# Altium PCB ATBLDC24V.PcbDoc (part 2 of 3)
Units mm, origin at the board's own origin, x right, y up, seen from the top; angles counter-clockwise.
Board outline 135 x 125 mm, 4 copper layers (Top Layer, GND, PWR/Signal, Bottom Layer), stack 1.716 mm thick; 340 components, 168 nets, 921 pads, 872 vias.
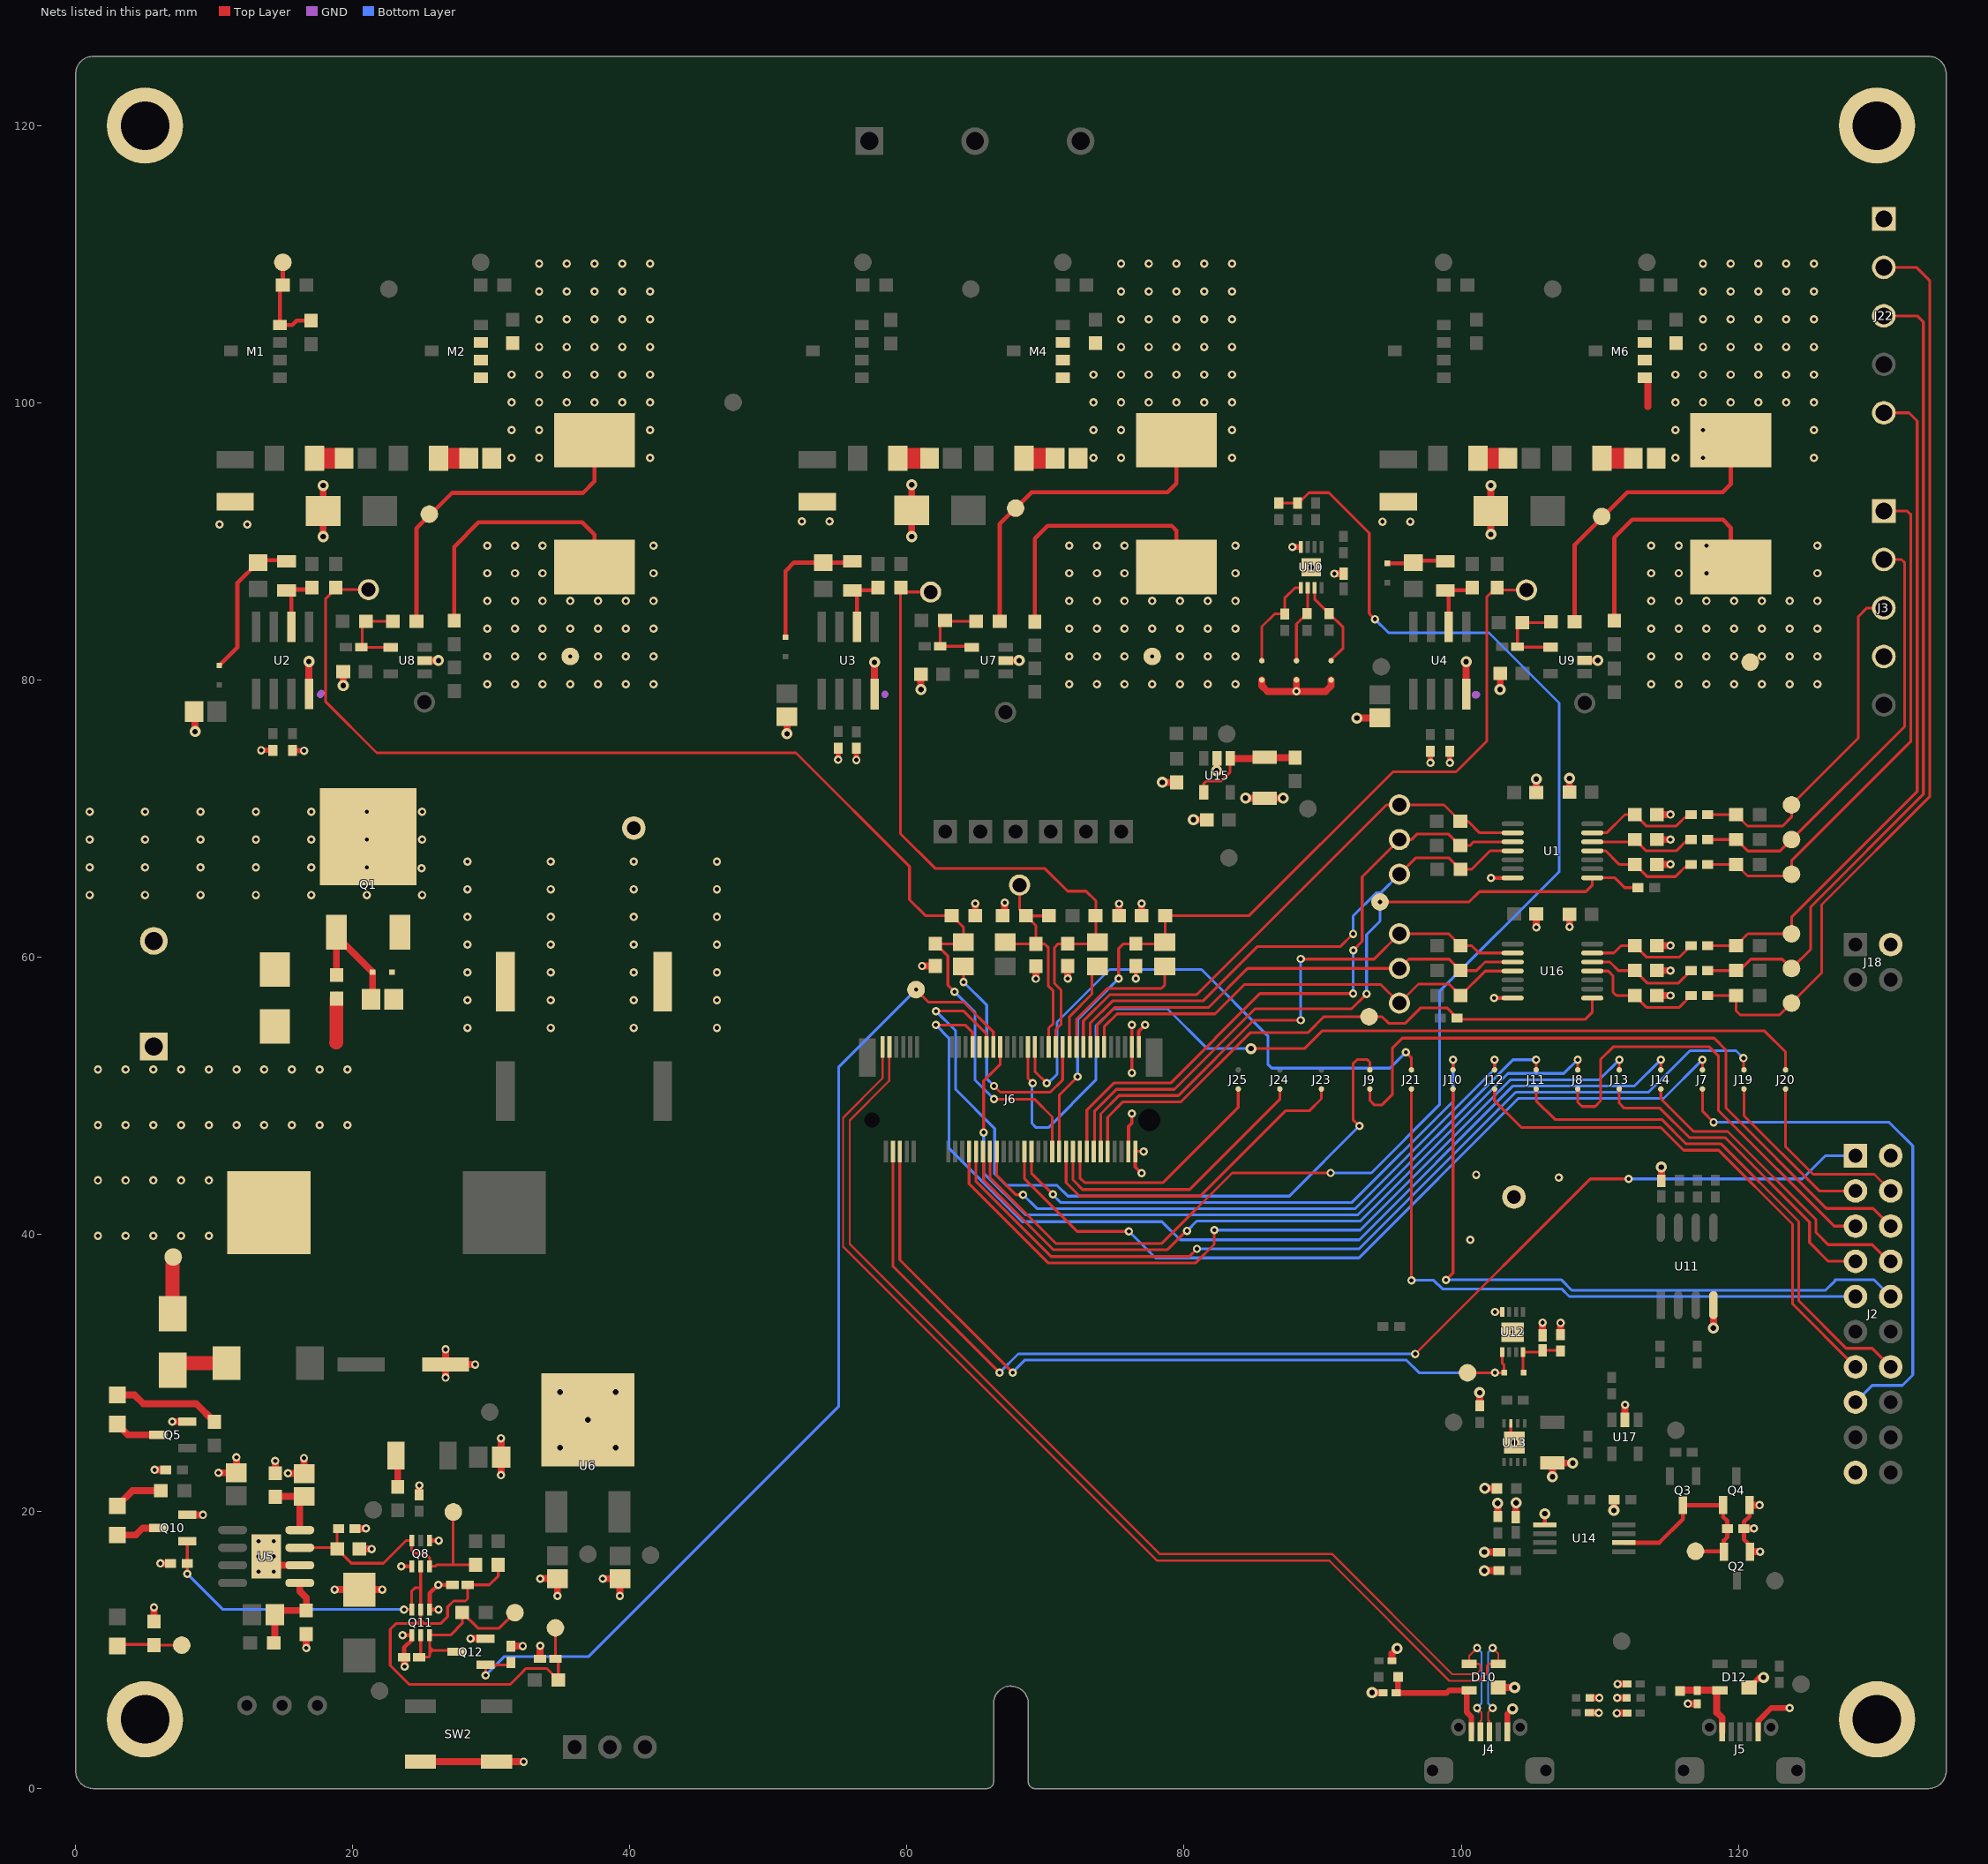
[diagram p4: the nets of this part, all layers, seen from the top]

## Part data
C1 C2 C39 C44 C45: library part A01-0087, "Ceramic capacitor, SMD 0603, X7R, 16V, +/-10 %"
C3 C8 C13: library part A01-0586, "Ceramic capacitor, SMD 1210, X7S , 50V, ±10%"
C4 C9 C14 C19 C23 C24: library part A01-0392, "Ceramic capacitor, SMD 0805, X7R, 50V, ±10 %"
C5 C10 C15: library part A01-0498, "CAP CER 4.7UF 50V 10% X5R 0805"
C6 C7 C11 C12 C16 C17: library part A01-0194, "Ceramic capacitor, SMD 0805, X7R, 50V, ±10 %"
C18 C20: library part A01-0721, "Cap Aluminum Lytic 220uF 50V 20% (10 X 10.2mm) SMD 150mA 2000h 105°C T/R"
C21 C30 C31 C55: library part A01-0321, "Ceramic capacitor, SMD 0402, C0G, 50V, +/-5%"
C22: library part A01-0394, "10uF/25V,SMD tantalum capacitor, precision molded chip, 6032-28 case,"
C25: library part A01-0283, "SMD aluminium electrolytic capasitor Ø8mm, Max rippel=0.25(@105degC, 100kHz), Tan=0.08"
C26 C57: library part A01-0214, "Ceramic capacitor, SMD 0805, X7R, 50V, ±10 %"
C27 C28: library part A01-0634, "Ceramic capacitor, SMD 0805, X5R, 25V, ±10%"
C29 C32: library part A01-0046, "Ceramic capacitor, SMD 0402, X7R, 25V, +/-10%"
C33 C34 C37: library part A01-0027, "Ceramic capacitor, SMD 0402, NP0, 50V, +/-10% (de16673)"
C35 C36 C38: library part A01-0367, "Ceramic capacitor, SMD 0603, X7R, 50V, ±10 %"
C40: library part A01-0381, "Capacitor, Ceramic, 1uF, 100V, 1206, X7R"
C41 C42 C43 C46 C47 C48: library part A01-0083, "Ceramic capacitor, SMD 0603, NP0, 50V,  ±5 %"
C49 C50 C56 C59: library part A01-0101, "Ceramic capacitor, SMD 0603, X7R, 50V, ±10 %"
C51: library part A01-0113, "Ceramic capacitor, SMD 0603, X7R, 50V, ±10 %"
C52 C54: library part A01-0050, "Ceramic capacitor, SMD 0402, X7R, 25V, +/-10%"
C53: library part A01-0038, "Ceramic capacitor, SMD 0402, X7R, 50V, +/-10%"
C60 C61 C65 C66: library part A01-0246, "Ceramic capacitor, SMD 0402, X7R, 16V, +/-10%"
C62: library part A01-0347, "Ceramic capacitor, SMD 0402, X5R, 6.3V, +/-20% (de33687)"
C63: library part A01-0324, "SMD tantalum capacitor, ESR = 1.7, 3216-18 (EIA) 1206,"
C64: library part A01-0377, "Ceramic capacitor, SMD 0603, X5R, 10V, 10% (de31036)"
CONN1: library part A08-2466, "PHOENIX CONTACT  GMKDS 3/ 2-7,62  TERMINAL BLOCK, WIRE TO BRD, 2POS, 12AWG"
CONN2: library part A08-2465, "TERMINAL BLOCK, WIRE TO BRD, 3POS, 12AWG"
D1 D3 D5 D18: library part A04-0049, "Schottky diode, If:200mA, Vf:0.35V, Vrrm:30V, SOD-523"
D2 D4 D6 D8: library part A04-0021, "Bidirectional Transient suppression diode, 600W, V(rm)=58.1V, I(rm)=1uA (at Vrm), V(br)=68V, V(cl)=121V (at Ipp = 33A), SMD (SMB package)"
D7: library part A04-0180, "Zener DIODE 28V, 500MW, SOD80"
D9: library part A04-0138, "1A, 100V, Schottky Barrier Rectifier, SMA"
D10 D12: library part A06-0236, "Double rail-to-rail USB ESD protection diode"
D11: library part A10-0019, "LED, Yellow, Wave length=591nm, SMD 0805, ±70°"
D13: library part A04-0133, "Zener diode SOD-523, 5.6V, 200mW"
D14 D15: library part A10-0017, "LED, Red, Wave length=639nm, SMD 0805, ±70°"
E1 E2 E3 E4 E5 E6: library part A08-0053, "2.8mm adhesive feet,diam 8.0mm"
F1: library part A02-0509, "SMD holder and fuse 5x20mm, Fast, 6.3A, 250V"
F2: library part A02-0504, "PolySwitch Resettable fuse 0.75A, 30V"
J1: library part A08-0191, "1x6 pin header, 2.54mm pitch, THM Pin-In-Paste"
J2: library part A08-1513, "Pin header, 2x10, Right Angle, 2.54mm, THM, Pin In Paste"
J3 J22: library part A08-2349, "SCREW-TERMINAL 5-POLE, 3.5MM, Through Hole"
J4 J5: library part A08-2112, "Micro USB AB Connector, Standard SMT + DIP"
J6: library part A08-2293, "M.2 (NGFF) Sockets for Adapter PCB"
J7 J8 J9 J10 J11 J12 J13 J14 J19 J20 J21 J23 J24 J25: library part A09-0473, "Default closed SMD strap"
J15 J16 J17: library part A08-1416
J18: library part A08-1519, "Pin header, 2x2, Right Angle, 2.54mm, THT, Pin In Paste"
J26: library part A08-1799, "1x3 pin header, 2.54mm pitch, Pin-in-Paste THM, 1mm hole"
JS1: library part A08-0543, "Jumper cap for 2.54mm pinheader"
L1 L6: library part A03-0035, "SMD RF inductor 0603. Z=470Ohm (@100MHz), Max R(dc)=0.65Ohm, Max current=1A"
L2 L3 L4 L5: library part A03-0004, "SMD RF inductor 0805. Z=1000Ohm (@100MHz), Max R(dc)=0.45Ohm, Max current=200mA"
LABEL1: library part A09-0611, "PCBA identification label PP Top White Gloss"
M1 M2 M3 M4 M5 M6: library part A05-0152, "60V, 4.7mA , 89A, Single N−Channel MOSFET, SO−8FL"
Q1: library part A05-0166, "MOSFET N-CH 60V 40A 16MOHM DPAK"
Q2 Q3: library part A05-0087, "P-ch. MOSFET. -30V, -3.7A continuous,RDS(ON)=0.05Ohm@VGS=-4,5V, RDS(ON)=0.08Ohm@VGS=-2.5V"
Q4 Q5 Q10: library part A05-0085, "N-Channel MOSFET. 60V, 0.300A continuous, 1.2A Peak. RDS(ON) = 3.8Ohm@VGS=4.5V, VGS(th)<2.5V"
Q8 Q11: library part A05-0051, "Dual N-Channel MOSFET, 60V, 115mA cont,RDS(ON) < 7.5 Ohm @50mA@5V, SOT-363"
Q12: library part A05-0001, "General purpose SMD small signal BJT transistor. Polarity:NPN, Body:SOT23, P(tot)=0.25W, V(ceo)=45V, I(c)=0.1A, h(fe)=200/450, f(t)=100MHz"
R1 R3 R4 R13 R14 R23 R24 R81 R82 R83 R84 R85 R86 R88 R89 R90 R91 R92 R93 R97 R101 R102 R112 R121: library part A02-0260, "Thick film resistor, SMD 0402, 1/16W, 1%"
R2 R9 R12 R19 R22 R29: library part A02-0994, "RESISTOR, 1206, 0R82, 1%, 0.5W"
R5 R15 R25: library part A02-0294, "Thick film resistor, SMD 0805, 0.125W, 1%"
R6 R16 R39 R41 R46 R49: library part A02-0960, "1.0K 0.1%, resistor in 0603 at 100mW, TEMPCO 10ppm/C, Max V=75V"
R7 R11 R17 R21 R27 R31 R33 R120: library part A02-0122, "Thick film resistor, SMD 0603, 1/10W, 1%"
R8 R10 R18 R20 R28 R47 R57 R58 R59: library part A02-0001, "Thick film resistor, SMD 0603, 1/10W, 1%"
R26 R30 R48: library part A02-0996, "RES, METAL STRIP, R02, 1%, 5W, SMD 4527"
R32: library part A02-0113, "Thick film resistor, SMD 0603, 1/10W, 1%"
R34: library part A02-0072, "Thick film resistor, SMD 0603, 1/10W, 1%"
R35: library part A02-0091, "Thick film resistor, SMD 0603, 1/10W, 1%"
R36: library part A02-0236, "Thick film resistor, SMD 0402, 1/16W, 1%"
R37 R42 R95 R98 R99: library part A02-0284, "Thick film resistor, SMD 0402, 1/16W, 1%"
R38: library part A02-0090, "Thick film resistor, SMD 0603, 1/10W, 1%"
R40 R67 R70 R72 R109 R110 R111: library part A02-0076, "Thick film resistor, SMD 0603, 1/10W, 1%"
R43: library part A02-0200, "Thick film resistor, SMD 0402, 1/16W, 1%"
R44 R45 R50 R51 R52 R53 R54 R56: library part A02-0959, "10K 0.1%, resistor in 0603 at 100mW, TEMPCO 10ppm/C, Max V=75V"
R55: library part A02-0026, "Thick film resistor, SMD 0603, 1/10W, 1%"
R60 R61 R63 R106 R107 R108: library part A02-0114, "Thick film resistor, SMD 0603, 1/10W, 1%"
R62 R123: library part A02-0082, "Thick film resistor, SMD 0603, 1/10W, 1%"
R64 R68 R74: library part A02-1013, "Thick film resistor, SMD 0603, 1/10W, 1%"
R65 R69 R75 R80: library part A02-0997, "Thick film resistor, SMD 0603, 1/10W, 1%"
R66 R71 R104 R118: library part A02-0252, "Thick film resistor, SMD 0402, 1/16W, 1%"
R73 R76 R78 R113 R114 R115: library part A02-0163, "RES 0.0 OHM 1/16W 0402 SMD"
R79: library part A02-1014, "Thick film resistor, SMD 0603, 1/10W, 1%"
R87: library part A02-0178, "Thick film resistor, SMD 0402, 1/16W, 1%"
R94: library part A02-0242, "Thick film resistor, SMD 0402, 1/16W, 1%"
R96: library part A02-0247, "Thick film resistor, SMD 0402, 1/16W, 1%"
R100: library part A02-0202, "Thick film resistor, SMD 0402, 1/16W, 1%"
R105: library part A02-0163, "Thick film resistor, SMD 0402, 1/16W, 1%"
R117: library part A02-0042, "Thick film resistor, SMD 0603, 1/10W, 1%"
R119: library part A02-0129, "Thick film resistor, SMD 0603, 1/10W, 1%"
R122: library part A02-0040, "Thick film resistor, SMD 0603, 1/10W, 1%"
SW1: library part A08-0947, "Slide Switch, right angle 3 pol, 2 pos, (de20049)"
SW2: library part A08-0091, "6.2x6.2 mm SMD tact switch"
TP1 TP2 TP5 TP7 TP8 TP9 TP10 TP11 TP12 TP14 TP15 TP17 TP18 TP20 TP27 TP38 TP39 TP40 TP41 TP42 TP43 TP44 TP45 TP46 TP47 TP48 TP49 TP50 TP51 TP52 TP53 TP54 TP55 TP56 TP57 TP58 TP60 TP61 TP62 TP63 TP64 TP65 TP66 TP67 TP68 TP72: library part A08-0004, "Single SMD testpad"
TP3 TP4 TP6 TP13 TP16 TP19 TP21 TP23 TP25 TP26 TP28 TP35 TP36: library part A08-1748, "Single thru-hole testpin"
TP22 TP24: library part A08-1716, "THM Test Point, Without Base, 1.0mm Dia. Mounting"
U1 U16: library part A06-0852, "4-BIT BIDIRECTIONAL VOLTAGE-LEVEL TRANSLATOR 14TSSOP"
U2 U3 U4: library part A06-1250, "High Voltage, High and Low Side MOSFET Driver"
U5: library part A06-1249, "5 V to 20 V Adjustable LDO with Adjustable Current Limit and 3.3 V Logic Compatible Enable Input"
U6: library part A06-0137, "3-Terminal Positive Voltage Regulator"
U7 U8 U9: library part A06-1252, "Op Amps High Temp RR Op Amp 2.5V to 5.5V"
U10: library part A06-0633, "SINGLE DIGITAL TEMPERATURE SENSOR W/ SERIAL EEPROM, UDFN8"
U11: library part A06-1051, "8Mbit SPI serial flash memory"
U12: library part A06-1276, "ATSHA204 with 1-wire interface and UDFN8 package"
U13: library part A06-0957, "500mA LDO, ADJ, low noise, 8-DFN package"
U14: library part A06-0068, "Autoswitching 2:1 Power Mux"
U15: library part A06-1285, "OP AMP, CMOS 1MHZ RRI/O, SOT-23-5"
U17: library part A06-1087, "Single channel power switch, 1A, reverse block, active low enabled."

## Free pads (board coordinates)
  round 5.5 hole 3.5: 1(5,5) 1(5,120) 1(130,5) 1(130,120)

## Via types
v1: diameter 0.6, hole 0.3, Top Layer to Bottom Layer, 769 vias
v2: diameter 0.8, hole 0.4, Top Layer to Bottom Layer, 92 vias
v3: diameter 1, hole 0.5, Top Layer to Bottom Layer, 11 vias

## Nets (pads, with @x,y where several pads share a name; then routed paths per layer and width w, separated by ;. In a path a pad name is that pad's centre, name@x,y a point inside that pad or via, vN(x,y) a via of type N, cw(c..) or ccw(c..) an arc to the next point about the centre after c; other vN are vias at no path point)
A0: J15.2 R81.2 U10.7 | length 6.5
  Top Layer w0.2: U10.7@89.417,86.647 89.417,85.831 R81.2@90.457,84.791 90.477,84.791 91.475,83.793 91.475,82.304 90.608,81.438 J15.2@90.608,81.382
A1: J16.2 R85.2 U10.6 | length 5.6
  Top Layer w0.2: J16.2@88.108,81.382 88.108,84.033 88.917,84.842 U10.6@88.917,86.647
A2: J17.2 R82.2 U10.5 | length 7.1
  Top Layer w0.2: J17.2@85.608,81.382 85.608,83.843 86.537,84.772 R82.2@87.257,84.772 ; R82.2@87.257,84.766 R82.2@87.257,84.772 ; U10.5@88.417,86.647 88.015,86.647 87.257,85.89 R82.2@87.257,84.772
BEMF_UADC: C49.1 J6.42 L2.1 R64.2 R65.2 TP21.1 | length 88.3
  Top Layer w0.2: TP21.1@21.135,86.512 18.697,86.512 18.031,85.846 18.031,78.437 21.73,74.738 51.983,74.738 60.179,66.542 60.179,64.138 61.316,63 R65.2@63.22,63 64.079,62.142 L2.1@64.079,61.075 63.959,61.075 63.844,60.96 C49.1@62.056,60.96 62.951,60.065 62.951,57.983 v1(63.43,57.502) ; v1(66.277,49.75) 69.196,49.75 70.48,48.466 J6.42@70.48,45.975
  Bottom Layer w0.2: v1(63.43,57.502) 64.907,56.026 64.907,51.12 v1(66.277,49.75)
BEMF_UN: J6.46 J23.2 | length 24.7
  Top Layer w0.2: J6.46@71.48,45.975 71.48,43.728 72.455,42.753 81.164,42.753 87.317,48.905 89.038,48.905 89.907,49.773 J23.2@89.907,50.482
BEMF_UP: J6.45 L2.2 | length 17.4
  Top Layer w0.2: v1(64.079,58.203) L2.2@64.079,59.325 ; v1(66.277,50.7) 66.727,50.25 70.346,50.25 71.23,51.133 J6.45@71.23,53.525
  Bottom Layer w0.2: v1(64.079,58.203) 65.751,56.532 65.751,51.226 v1(66.277,50.7)
BEMF_VADC: C50.1 J6.43 L3.1 R68.2 R69.2 TP23.1 | length 49.9
  Top Layer w0.2: R68.2@59.539,86.657 59.528,86.668 59.528,68.906 62.048,66.386 69.963,66.386 71.592,64.756 72.924,64.756 73.633,64.047 L3.1@73.633,61.175 ; R68.2@59.55,86.668 59.875,86.342 TP23.1@61.708,86.342 ; J6.43@70.73,53.525 70.73,54.739 71.122,55.131 71.122,57.617 70.65,58.089 70.65,60.7 70.91,60.96 C50.1@71.586,60.96 73.418,60.96 L3.1@73.633,61.175 ; L3.1@73.733,61.075 L3.1@73.633,61.175
BEMF_VN: J6.48 J24.2 | length 20.7
  Top Layer w0.2: J6.48@71.98,45.975 71.98,43.921 72.667,43.235 80.407,43.235 86.907,49.735 J24.2@86.907,50.482
BEMF_VP: J6.47 L3.2 | length 6.4
  Top Layer w0.2: J6.47@71.73,53.525 71.73,55.723 73.348,57.341 L3.2@73.348,59.299
BEMF_WADC: C56.1 J6.44 L4.1 R74.2 R75.2 TP25.1 | length 64
  Top Layer w0.2: J6.44@70.98,45.975 70.98,50.032 v1(72.316,51.367) ; v1(75.277,58.45) 75.277,60.606 75.632,60.96 C56.1@76.514,60.96 78.485,60.96 L4.1@78.6,61.075 78.633,61.108 R75.2@78.633,63 84.708,63 95.076,73.369 99.622,73.369 101.851,75.597 101.851,86.011 102.594,86.753 102.854,86.492 TP25.1@104.708,86.492
  Bottom Layer w0.2: v1(72.316,51.367) 72.316,55.488 v1(75.277,58.45)
BEMF_WN: J6.50 J25.2 | length 17.1
  Top Layer w0.2: J6.50@72.48,45.975 72.48,44.057 72.804,43.733 78.484,43.733 83.907,49.157 J25.2@83.907,50.482
BEMF_WP: J6.49 L4.2 | length 10.7
  Top Layer w0.2: J6.49@72.23,53.525 72.23,55.52 74.448,57.738 78.358,57.738 78.6,57.98 L4.2@78.6,59.325
EDBG_ID1: D18.2 J6.6 TP62.1 U12.5 | length 59.1
  Top Layer w0.2: J6.6@59.48,45.975 59.48,38.156 v1(67.627,30.01) ; TP62.1@100.453,30.003 100.46,30.01 v1(102.427,30.01) D18.2@103.099,30.01 103.099,30.552 102.961,30.691 U12.5@102.961,31.493
  Bottom Layer w0.2: v1(67.627,30.01) 67.627,30.056 68.487,30.916 96.049,30.916 96.956,30.01 v1(102.427,30.01)
EDBG_ID2: J2.1@128.46,45.669 J6.4 | length 87.4
  Top Layer w0.2: J6.4@58.98,45.975 58.98,37.706 v1(66.677,30.01) ; v1(96.684,31.366) 109.319,44.002 109.321,44 v1(112.077,44)
  Bottom Layer w0.2: v1(66.677,30.01) 68.034,31.366 v1(96.684,31.366) ; v1(112.077,44) 124.612,44 126.281,45.669 J2.1@128.46,45.669
EDBG_USB_HS_N: D10.3 J4.2 J6.3 | length 82.8
  Top Layer w0.15: J6.3@58.73,53.525 58.72,53.515 58.72,51.071 55.864,48.214 55.864,39.299 78.222,16.94 90.661,16.94 99.348,8.254 101.084,8.254 101.385,8.555 101.385,8.877 101.264,8.998 D10.3@100.92,8.998 ; D10.3@100.575,8.998 100.575,9.577 v1(101.146,10.148) ; v1(101.146,5.822) 101.465,5.503 101.465,4.941 101.38,4.856 J4.2@101.38,4.1
  GND w0.15: 101.24,5.493 v1@101.24,5.624
  Bottom Layer w0.15: v1(101.146,5.822) 101.465,6.142 101.465,9.828 v1(101.146,10.148)
EDBG_USB_HS_P: D10.2 J4.3 J6.1 | length 84.5
  Top Layer w0.15: J6.1@58.23,53.525 58.24,53.515 58.24,51.27 55.384,48.413 55.384,39.1 78.024,16.46 90.462,16.46 99.149,7.774 101.283,7.774 101.865,8.356 101.865,8.877 101.986,8.998 D10.2@102.675,8.998 102.675,9.738 v1(102.265,10.148) ; J4.3@102.03,4.1 102.03,4.856 101.945,4.941 101.945,5.503 v1(102.265,5.822)
  Bottom Layer w0.15: v1(102.265,5.822) 101.945,6.142 101.945,9.828 v1(102.265,10.148)
ENCODER_A: J6.55 R107.1 TP35.1 U16.3 | length 34.1
  Top Layer w0.2: J6.55@73.73,53.525 73.73,55.111 74.976,56.357 81.756,56.357 84.579,59.181 TP35.1@95.538,59.181 96.21,59.852 99.13,59.852 R107.1@99.955,59.027 101.099,59.027 101.717,59.646 U16.3@103.711,59.646
ENCODER_B: J6.56 R106.1 TP26.1 U16.2 | length 41
  Top Layer w0.2: J6.56@73.98,45.975 73.98,48.69 75.302,50.011 79.593,50.011 85.023,55.441 v1(88.415,55.441) ; v1(88.415,59.866) 88.433,59.848 93.706,59.848 TP26.1@95.538,61.681 99.102,61.681 R106.1@99.955,60.827 100.748,60.827 101.28,60.296 U16.2@103.711,60.296
  Bottom Layer w0.2: v1(88.415,55.441) v1(88.415,59.866)
ENCODER_EN: J6.58 R112.1 TP72.1 U16.8 | length 43.6
  Top Layer w0.2: J6.58@74.48,45.975 74.477,45.979 74.477,48.435 75.604,49.561 79.78,49.561 84.763,54.544 88.927,54.544 90.081,55.698 TP72.1@93.346,55.698 94.291,55.698 94.294,55.696 ; TP72.1@93.346,55.696 94.294,55.696 ; R112.1@99.7,55.5 108.921,55.5 109.461,56.04 U16.8@109.461,57.046 ; R112.1@99.7,55.6 99.7,55.62 98.996,56.325 97.058,56.325 95.963,55.23 94.76,55.23 94.294,55.696
ENCODER_Z: J6.57 R108.1 TP36.1 U16.4 | length 34.4
  Top Layer w0.2: J6.57@74.23,53.525 74.23,54.975 75.163,55.907 82.231,55.907 84.346,58.022 94.197,58.022 TP36.1@95.538,56.681 96.91,58.052 99.13,58.052 R108.1@99.955,57.227 101.723,58.996 U16.4@103.711,58.996
EXT1_RXD: J6.26 J12.2 | length 44.2
  Top Layer w0.2: J6.26@66.48,45.975 66.48,44.23 67.861,42.85 v1(68.377,42.85) ; J12.2@102.407,51.863 v1(102.407,52.596)
  Bottom Layer w0.2: v1(68.377,42.85) 69.374,41.852 92.355,41.852 102.407,51.905 v1(102.407,52.596)
EXT1_TXD: J6.27 J11.2 | length 56.1
  Top Layer w0.2: v1(65.527,47.35) 65.527,51.062 66.73,52.265 J6.27@66.73,53.525 ; J11.2@105.407,51.863 v1@105.407,52.568
  Bottom Layer w0.2: v1(65.527,47.35) 65.527,44.412 68.537,41.403 92.541,41.403 103.735,52.596 v1(105.407,52.596)
GND: C1.2 C2.2 C3.2 C4.2 C8.2 C9.2 C13.2 C14.2 C18.2 C20.2 C21.2 C22.2 C23.2 C24.2 C25.2 C26.2 C27.2 C28.2 C29.1 C30.2 C31.2 C32.1 C35.2 C36.2 C38.2 C39.1 C40.2 C41.2 C42.2 C43.2 C44.2 C45.2 C46.2 C47.2 C48.2 C49.2 C50.2 C51.2 C52.2 C53.2 C54.2 C55.2 C56.2 C57.2 C59.2 C60.1 C61.2 C62.2 C63.2 C64.2 C65.2 C66.2 D2.2 D4.2 D6.2 D10.1 D12.1 D13.2 J2.2@131,45.669 J2.19@128.46,22.809 J3.4 J4.5 J5.5 J6.64 J6.65 J6.66 J6.67 J15.1 J16.1 J17.1 J18.2@131,60.909 J22.1 pad.1 Q1.3 Q2.1 Q4.2 Q5.2 Q8.1 Q8.4 Q10.2 Q11.1 Q11.4 Q12.2 R3.1 R4.2 R13.1 R14.2 R23.1 R24.2 R26.1 R30.1 R34.1 R35.2 R36.1 R37.1 R39.1 R40.1 R41.1 R42.1 R48.1 R49.1 R56.1 R65.1 R66.1 R69.1 R71.1 R75.1 R80.1 R93.1 R94.2 R98.1 R99.1 R100.1 R101.1 R118.1 R121.1 SW2.3 SW2.4 TP22.1 TP24.1 TP52.1 TP53.1 TP57.1 U1.7 U2.4 U3.4 U4.4 U5.2 U5.9 U6.2 U7.2 U8.2 U9.2 U10.4 U10.9 U11.4 U12.4 U12.9 U13.7 U13.9 U14.5 U15.2 U16.7 U17.2 | length 221.2
  Top Layer w0.2: J6.66@76.48,45.975 v1(77.079,45.975) ; v1(102.427,34.397) 102.431,34.393 U12.4@102.961,34.393
  Top Layer w0.25: J6.64@75.98,45.975 75.98,47.774 76.227,48.02 v1(76.227,48.7) ; v1(76.22,51.65) 76.23,51.661 J6.65@76.23,53.525 v1(76.23,55.101) ; J6.66@76.48,45.975 76.48,44.855 v1(76.935,44.4) ; J6.67@76.73,53.525 76.73,54.646 v1(77.185,55.101) ; U13.7@103.584,26.367 103.584,25.217 v2(103.834,24.967)
  Top Layer w0.3: v1(23.496,16.046) Q8.1@24.239,16.046 ; v1(23.602,11.075) Q11.1@24.25,11.075 24.25,10.725 23.698,10.174 C53.2@23.698,9.486 ; Q8.4@25.539,17.896 v1(26.196,17.896) ; v1(26.187,12.925) Q11.4@25.55,12.925 25.55,14.084 v1(26.166,14.7) C52.2@27.19,14.7 ; R41.1@27.317,84.273 27.317,89.608 29.084,91.375 36.558,91.375 37.45,90.483 R30.1@37.45,88.147 ; R39.1@69.221,84.192 69.221,90.197 70.148,91.123 79.111,91.123 79.45,90.784 R26.1@79.45,88.147 ; v1(76.514,58.448) C56.2@76.514,59.36 ; v1(102.147,65.718) U1.7@103.711,65.718 ; v1(102.375,57.046) U16.7@103.711,57.046 ; U14.5@106.034,19.042 v2(106.034,19.838) ; R49.1@111.043,84.269 111.043,90.271 112.334,91.562 118.889,91.562 119.45,91 R48.1@119.45,88.147 ; Q4.2@120.8,20.45 120.8,19.635 120.406,19.241 R101.1@120.406,18.767 120.406,17.98 120.85,17.536 Q2.1@120.85,17.1
  Top Layer w0.4: v1(13.389,74.925) R3.1@14.226,74.925 ; R4.2@15.646,74.895 v1(16.483,74.895) ; v1(55.035,74.244) R13.1@55.035,75.081 ; v1(56.343,74.226) R14.2@56.343,75.063 ; v1(87.807,89.597) 88.265,89.597 ; v1(97.775,74.019) R23.1@97.775,74.856 ; v1(99.175,74.019) R24.2@99.175,74.856 ; J4.5@103.33,4.1 103.33,5.386 v2(103.71,5.765) ; D12.1@120.775,7.297 121.5,8.022 v2(121.817,8.022) ; J5.5@121.43,4.1 121.43,4.872 122.365,5.807 v1(123.711,5.807)
  Top Layer w0.5: R40.1@5.65,12.05 v1(5.65,13.072) ; v1(5.702,23) R66.1@6.5,23 ; v1(6.104,16.25) R71.1@6.85,16.25 ; v1(6.968,26.479) Q5.2@8.05,26.479 ; Q10.2@8.05,19.75 v1(9.184,19.75) ; C4.2@8.542,77.709 8.614,77.637 v2(8.614,76.274) ; v1(10.305,22.787) C23.2@11.595,22.787 11.595,23.895 v1(11.6,23.9) ; U5.9@13.75,16.75 14.385,16.115 U5.2@16.175,16.115 ; R34.1@14.4,22.75 v1(14.4,23.644) ; v1(15.327,22.75) 16.476,22.75 C24.2@16.5,22.725 16.477,22.748 v1(16.477,23.85) ; v1(16.64,10.15) 16.64,10.797 R35.2@16.652,10.808 ; U2.4@16.833,78.987 v2(16.833,81.332) ; v2(17.857,90.343) D2.2@17.857,92.188 v2(17.857,94.033) ; v1(18.688,14.36) C22.2@20.47,14.36 v1(22.129,14.36) ; v2(19.31,79.598) C36.2@19.31,80.608 ; R36.1@20.164,18.768 v1(20.946,18.768) ; C51.2@20.471,17.289 v1(21.36,17.289) ; C53.2@23.698,9.486 23.74,9.444 v1(23.74,8.801) ; R118.1@24.797,21.205 v1(24.797,21.881) ; SW2.3@24.885,1.941 SW2.4@30.385,1.941 v1(32.335,1.941) ; U8.2@25.175,81.4 v2(26.182,81.4) ; v1(26.7,29.654) C25.2@26.7,30.6 ; v1(26.7,31.692) C25.2@26.7,30.6 ; v1(28.493,10.825) Q12.2@29.591,10.825 ; v1(28.833,30.6) C25.2@26.7,30.6 ; v1(30.702,22.618) C26.2@30.702,23.918 v1(30.702,25.283) ; R121.1@31.414,10.285 v1(32.272,10.285) ; C54.2@33.523,9.367 v1(33.523,10.297) ; v1(33.525,15.151) C27.2@34.767,15.151 v1(34.767,13.904) ; v1(38.037,15.145) C28.2@39.278,15.145 v1(39.278,13.898) ; v2(51.338,76.112) C9.2@51.338,77.358 ; U3.4@57.655,78.975 v2(57.655,81.27) ; v2(60.335,90.343) D4.2@60.335,92.231 v2(60.335,94.076) ; v2(61,79.312) C35.2@61,80.4 ; v1(61.087,59.36) C49.2@62.056,59.36 ; R65.1@64.92,63 v1(64.92,63.872) ; R80.1@67.052,63.232 v1(67.052,63.922) ; U7.2@67.125,81.4 v2(68.093,81.4) ; v1(69.3,58.437) C59.2@69.3,59.35 ; v1(71.599,58.458) C50.2@71.599,59.336 ; R69.1@75.297,62.977 v1(75.297,63.848) ; R75.1@76.933,63 v1(76.933,63.871) ; v2(78.426,72.609) R56.1@79.473,72.609 ; v2(80.671,69.912) C39.1@81.635,69.912 ; v2@82.371,73.471 U15.2@82.371,74.333 ; v2(84.432,71.467) C40.2@85.798,71.467 v2(87.149,71.467) ; J17.1@85.608,80.002 85.608,79.576 86.008,79.176 v1(88.108,79.176) ; J16.1@88.108,80.002 v1(88.108,79.176) ; J15.1@90.608,80.002 90.608,79.57 90.215,79.176 v1(88.108,79.176) ; v1(90.845,87.666) C60.1@91.507,87.666 ; v2(92.469,77.25) C14.2@93.845,77.25 ; v2(93.567,6.923) C30.2@94.357,6.923 ; C31.2@95.007,9.223 95.007,9.738 v2(95.376,10.107) ; U4.4@100.355,78.975 v2(100.355,81.323) ; R94.2@101.334,27.617 v2(101.334,28.571) ; v2(101.663,15.726) R98.1@102.722,15.726 ; v2(101.675,17.067) C65.2@102.734,17.067 ; v2(101.707,21.667) C64.2@102.585,21.667 ; v2(102.137,90.507) D6.2@102.137,92.188 v2(102.137,94.033) ; R99.1@102.634,19.642 v2(102.634,20.596) ; D10.1@102.675,7.298 v2(103.852,7.298) ; v2(102.8,79.3) 102.821,79.321 C38.2@102.821,80.466 C38.2@103.008,80.279 ; C66.2@103.934,19.592 103.934,20.6 v2(103.957,20.623) ; v1(105.416,62.14) C45.2@105.416,63.108 ; C2.2@105.416,71.868 v2(105.416,72.846) ; C62.2@105.867,32.714 v1(105.867,33.624) ; v2(106.584,22.499) C63.2@106.584,23.492 v2(108.049,23.492) ; R93.1@107.167,32.764 v1(107.167,33.605) ; v1(107.816,62.189) C44.2@107.816,63.081 ; C1.2@107.816,71.918 v2(107.816,72.896) ; U9.2@108.886,81.409 v2(109.852,81.409) ; C29.1@109.249,5.473 v1(109.928,5.473) ; R37.1@109.289,6.547 v1(109.968,6.547) ; v2(111.017,20.072) 111.034,20.089 R100.1@111.034,20.842 ; v1(111.235,5.447) C32.1@111.964,5.447 ; v1(111.261,6.547) R42.1@111.939,6.547 ; v1(111.285,7.547) C55.2@111.964,7.547 ; U17.2@111.822,26.601 v1(111.822,27.687) ; C48.2@114.13,57.228 v1(115.098,57.228) ; C46.2@114.13,59.028 v1(115.098,59.028) ; C47.2@114.13,60.828 v1(115.098,60.828) ; C43.2@114.13,66.691 v1(115.098,66.691) ; C41.2@114.131,68.484 v1(115.099,68.484) ; C42.2@114.131,70.284 v1(115.099,70.284) ; C61.2@114.445,43.84 v2(114.445,44.845) ; v1(116.36,6.122) C21.2@117.039,6.122 ; v2(118.205,33.236) U11.4@118.205,34.89 ; R101.1@120.406,18.767 v1(121.134,18.767) ; Q4.2@120.8,20.45 v1(121.528,20.45) ; Q2.1@120.85,17.1 v1(121.578,17.1)
  GND w0.5: v1(11.6,23.9) v1@11.6,23.958 ; 17.65,78.95 17.737,79.037 ; 58.4,78.95 58.415,78.966 ; 101.007,78.92 101.089,78.92 101.107,78.938 101.012,78.938 101,78.95 101.054,78.95 ; v2@103.9,20.68 v2(103.957,20.623)
  Bottom Layer w0.5: v1@23.711,8.771 v1(23.74,8.801)
  other v1: 13.2,15.65 14.3,15.65 13.2,16.75 14.3,16.75 13.2,17.85 14.3,17.85 103.711,32.943 100.647,39.604 107.039,44.087 101.084,44.294 28.281,54.897 34.281,54.897 40.281,54.897 46.281,54.897 28.281,56.897 34.281,56.897 40.281,56.897 46.281,56.897 28.281,58.897 34.281,58.897 40.281,58.897 46.281,58.897 28.281,60.897 34.281,60.897 40.281,60.897 46.281,60.897 28.281,62.897 34.281,62.897 40.281,62.897 46.281,62.897 28.281,64.897 34.281,64.897 40.281,64.897 46.281,64.897 28.281,66.897 34.281,66.897 40.281,66.897 46.281,66.897 29.7,79.697 31.7,79.697 33.7,79.697 35.7,79.697 37.7,79.697 39.7,79.697 41.7,79.697 71.7,79.697 73.7,79.697 75.7,79.697 77.7,79.697 79.7,79.697 81.7,79.697 83.7,79.697 113.7,79.697 115.7,79.697 117.7,79.697 119.7,79.697 121.7,79.697 123.7,79.697 125.7,79.697 29.7,81.697 31.7,81.697 33.7,81.697 35.7,81.697 37.7,81.697 39.7,81.697 41.7,81.697 71.7,81.697 73.7,81.697 75.7,81.697 77.7,81.697 79.7,81.697 81.7,81.697 83.7,81.697 113.7,81.697 115.7,81.697 117.7,81.697 119.7,81.697 121.7,81.697 123.7,81.697 125.7,81.697 29.7,83.697 31.7,83.697 33.7,83.697 35.7,83.697 37.7,83.697 39.7,83.697 41.7,83.697 71.7,83.697 73.7,83.697 75.7,83.697 77.7,83.697 79.7,83.697 81.7,83.697 83.7,83.697 113.7,83.697 115.7,83.697 117.7,83.697 119.7,83.697 121.7,83.697 123.7,83.697 125.7,83.697 29.7,85.697 31.7,85.697 33.7,85.697 35.7,85.697 37.7,85.697 39.7,85.697 41.7,85.697 71.7,85.697 73.7,85.697 75.7,85.697 77.7,85.697 79.7,85.697 81.7,85.697 83.7,85.697 113.7,85.697 115.7,85.697 117.7,85.697 119.7,85.697 121.7,85.697 123.7,85.697 125.7,85.697 29.7,87.697 31.7,87.697 33.7,87.697 41.7,87.697 71.7,87.697 73.7,87.697 75.7,87.697 83.7,87.697 113.7,87.697 115.7,87.697 117.7,87.697 125.7,87.697 29.7,89.697 31.7,89.697 33.7,89.697 41.7,89.697 71.7,89.697 73.7,89.697 75.7,89.697 83.7,89.697 113.7,89.697 115.7,89.697 117.7,89.697 125.7,89.697 10.379,91.226 12.379,91.226 52.405,91.432 54.405,91.432 94.322,91.421 96.322,91.421
  other v2: 34.969,24.612 38.969,24.612 36.969,26.612 34.969,28.612 38.969,28.612 82.35,73.45 89.167,88.122
GND_E: CONN1.2 D8.2 Q1.2
  other v1: 1.007,64.482 5.007,64.482 9.007,64.482 13.007,64.482 17.007,64.482 21.007,64.482 25.007,64.482 24.956,66.406 1.007,66.482 5.007,66.482 9.007,66.482 13.007,66.482 17.007,66.482 21.007,66.482 1.007,68.482 5.007,68.482 9.007,68.482 13.007,68.482 17.007,68.482 21.007,68.482 25.007,68.482 1.007,70.482 5.007,70.482 9.007,70.482 13.007,70.482 17.007,70.482 21.007,70.482 25.007,70.482
GPIO1: J6.18 J13.2 | length 59.1
  Top Layer w0.2: J6.18@64.48,45.975 64.48,43.64 70.182,37.938 80.837,37.938 82.168,39.269 82.168,40.289 v1(82.177,40.297) ; J13.2@111.407,51.863 v1@111.407,52.641
  Bottom Layer w0.2: v1(82.177,40.297) 92.708,40.297 103.565,51.154 109.965,51.154 v1(111.407,52.596)
GPIO2: J6.19 J14.2 | length 73.4
  Top Layer w0.2: v1(62.08,55.101) 64.203,55.101 64.73,54.574 J6.19@64.73,53.525 ; J14.2@114.407,51.863 v1(114.407,52.596)
  Bottom Layer w0.2: v1(62.08,55.101) 63.02,54.161 63.02,46.218 68.33,40.909 78.402,40.909 79.714,39.597 92.645,39.597 103.752,50.704 112.515,50.704 v1(114.407,52.596)
GPIO3: J6.20 J19.2 | length 66.9
  Top Layer w0.2: J6.20@64.98,45.975 64.98,43.801 70.394,38.388 80.368,38.388 v1(80.927,38.947) ; J19.2@120.372,51.976 v1@120.372,52.701
  Bottom Layer w0.2: v1(80.927,38.947) 92.631,38.947 103.938,50.254 113.527,50.254 116.519,53.246 119.835,53.246 v1(120.372,52.709)
GPIO4: J6.21
GPIO5: J6.22 J8.2 | length 53.5
  Top Layer w0.2: J6.22@65.48,45.975 65.53,45.925 65.53,43.908 70.548,38.89 78.799,38.89 80.179,40.269 80.201,40.247 v1(80.214,40.247) ; J8.2@108.407,51.863 v1@108.407,52.595
  Bottom Layer w0.2: v1(80.214,40.247) 80.92,40.953 92.728,40.953 103.379,51.604 107.414,51.604 v1(108.407,52.597)
GPIO6: J6.23 J9.2 | length 54.5
  Top Layer w0.2: v1(62.1,56.1) 64.094,56.1 65.73,54.464 J6.23@65.73,53.525 ; v1(92.647,47.809) 92.194,48.262 92.194,52.317 92.481,52.604 93.221,52.604 93.407,52.418 J9.2@93.407,51.863
  Bottom Layer w0.2: v1(62.1,56.1) 63.519,54.681 63.519,50.446 66.33,47.635 66.33,44.38 67.182,43.528 70.833,43.528 71.609,42.752 87.591,42.752 v1(92.647,47.809)
GPIO7: J6.24 R86.2 R87.2 | length 103.2
  Top Layer w0.2: J6.24@65.98,45.975 65.98,44.094 70.735,39.34 78.388,39.34 83.472,44.423 v1(90.573,44.423) ; R86.2@86.837,92.762 R87.2@88.187,92.762 88.267,92.762 89.017,93.512 90.451,93.512 93.365,90.598 93.365,84.797 v1(93.779,84.382)
  Bottom Layer w0.2: v1(90.573,44.423) 93.511,44.423 98.429,49.341 98.429,57.519 107.066,66.156 107.066,78.334 102.004,83.396 94.765,83.396 v1(93.779,84.382)
GPIO8: J6.25 Q12.1 R121.2 TP45.1 | length 76.5
  Top Layer w0.2: v1(29.591,8.173) Q12.1@29.591,8.925 31.254,8.925 R121.2@31.414,9.085 ; v1(60.65,57.65) 61.55,56.75 64.081,56.75 66.23,54.601 J6.25@66.23,53.525
  Bottom Layer w0.2: v1@29.568,8.151 v1(29.591,8.173) 30.95,9.532 37.038,9.532 55.062,27.556 55.062,52.062 v1(60.65,57.65)
GPIO9/ADC: J6.34 J7.2 | length 60
  Top Layer w0.2: J6.34@68.48,45.975 68.48,44.001 72.273,40.209 v1(76.018,40.209) ; J7.2@117.407,51.863 v1@117.407,52.588
  Top Layer w0.254: v1(76.018,40.209) v1@76.06,40.209
  Bottom Layer w0.2: v1(76.018,40.209) 77.93,38.297 80.657,38.297 ; 80.658,38.297 81.196,38.297 92.618,38.297 104.124,49.804 114.615,49.804 v1(117.407,52.596)
GPIO10: J6.35 J20.2 | length 69.7
  Top Layer w0.2: J6.35@68.73,53.525 68.73,51.246 v1(69.077,50.9) ; v2(84.827,53.4) 88.679,53.4 89.953,54.673 121.892,54.673 123.407,53.158 J20.2@123.407,51.863
  Bottom Layer w0.2: v1(69.077,50.9) 69.027,50.85 69.027,47.989 69.316,47.7 70.204,47.7 73.623,51.119 73.623,55.002 74.896,56.274 78.795,56.274 81.67,53.4 v2(84.827,53.4)
GPIO11: J6.36 J10.2 | length 39.6
  Top Layer w0.2: J6.36@68.98,45.975 68.98,44.42 v1(70.522,42.878) ; J10.2@99.407,51.863 v1(99.407,52.596)
  Bottom Layer w0.2: v1@70.512,42.868 71.078,42.302 92.124,42.302 99.407,49.585 v1(99.407,52.596)
GPIO12: J6.37 J21.2 | length 40.6
  Top Layer w0.2: J6.37@69.23,53.525 69.23,51.746 v1(70.077,50.9) ; v1(96.002,53.133) 96.407,52.728 J21.2@96.407,51.863
  Bottom Layer w0.2: v1(70.077,50.9) 70.188,50.9 70.835,51.546 70.835,55.314 74.624,59.103 81.252,59.103 86.044,54.312 86.044,52.269 86.328,51.984 94.853,51.984 v1(96.002,53.133)
HALL1: J6.51 R60.1 TP3.1 U1.2 | length 40.1
  Top Layer w0.2: J6.51@72.73,53.525 72.73,55.384 74.634,57.288 80.917,57.288 94.61,70.981 TP3.1@95.538,70.981 98.757,70.981 R60.1@99.932,69.806 100.491,69.806 101.329,68.968 U1.2@103.711,68.968
HALL2: J6.52 R61.1 TP4.1 U1.3 | length 47
  Top Layer w0.2: J6.52@72.98,45.975 72.98,48.963 74.929,50.911 79.02,50.911 85.475,57.366 v1(92.197,57.366) ; v1(92.206,60.498) 92.85,61.142 92.85,65.792 TP4.1@95.538,68.481 96.408,68.481 96.8,68.873 99.089,68.873 99.914,68.048 R61.1@99.939,68.048 100.618,68.048 100.888,68.318 U1.3@103.711,68.318
  Bottom Layer w0.2: v1(92.197,57.366) 92.206,57.375 v1(92.206,60.498)
HALL3: J6.53 R63.1 TP6.1 U1.4 | length 38.8
  Top Layer w0.2: J6.53@73.23,53.525 73.23,55.248 74.82,56.838 81.365,56.838 85.276,60.749 91.268,60.749 v1(92.2,61.68) ; TP6.1@95.538,65.981 96.712,67.154 99.13,67.154 R63.1@99.955,66.329 100.752,66.329 102.09,67.668 U1.4@103.711,67.668
  Bottom Layer w0.2: v1(92.2,61.68) 92.2,62.962 93.869,64.631 94.188,64.631 TP6.1@95.538,65.981
HALL_TRX_OE: J6.54 R1.1 TP60.1 U1.8 | length 53
  Top Layer w0.2: J6.54@73.48,45.975 73.53,46.025 73.53,48.877 75.115,50.461 79.299,50.461 85.112,56.274 92.093,56.274 v1(93.165,57.347) ; v1(94.138,63.981) 100.57,63.981 101.31,64.722 108.989,64.722 109.461,65.193 U1.8@109.461,65.718 111.089,65.718 111.793,65.014 R1.1@112.761,65.014
  Bottom Layer w0.2: v1(93.165,57.347) 93.165,61.622 94.138,62.596 v1(94.138,63.981)
INPUT_VOLTAGE_DETECTED: Q2.2 Q3.3 Q4.1 R101.2 TP65.1 U14.2 | length 14.2
  Top Layer w0.3: U14.2@111.734,17.742 114.297,17.742 116.004,19.449 Q3.3@116.004,20.142 ; Q3.3@116.012,20.449 118.899,20.449 Q4.1@118.9,20.45 118.9,19.613 119.206,19.307 R101.2@119.206,18.767 119.206,18.155 118.95,17.899 Q2.2@118.95,17.1 118.923,17.128 TP65.1@116.909,17.128
  Top Layer w0.5: Q3.3@116.004,20.142 Q3.3@116.034,20.112
MOTOR_VDC: C59.1 J6.41 L5.1 R79.2 R80.2 TP28.1 | length 16.7
  Top Layer w0.2: L5.1@67.1,61.075 67.225,60.95 C59.1@69.3,60.95 ; TP28.1@68.12,65.2 68.12,63.448 R80.2@68.59,62.977 69.3,62.268 C59.1@69.3,60.95 ; R80.2@68.956,62.977 R79.2@70.24,62.977 ; J6.41@70.23,53.525 70.23,54.876 70.555,55.2 70.555,57.548 70.2,57.903 70.2,60.684 69.933,60.95 C59.1@69.3,60.95
NetC5_1: C5.1 D1.1 R5.2 | length 10.8
  Top Layer w0.3: D1.1@10.357,81.038 11.667,82.347 11.667,86.994 R5.2@13.165,88.493 ; R5.2@12.631,88.637 C5.1@14.831,88.637
NetC5_2: C5.2 R8.1 U2.6 | length 4.7
  Top Layer w0.3: U2.6@15.563,83.837 15.563,86.179 15.216,86.526 16.871,86.526 R8.1@17.049,86.703
NetC6_1: C6.1 R2.1 | length 1.9
  Top Layer w1.5: R2.1@17.335,96 C6.1@19.235,96
NetC7_1: C7.1 R9.1 | length 1.8
  Top Layer w1.5: R9.1@26.335,96 C7.1@28.1,96
NetC7_2: C7.2 M2.1 R11.1 R16.1 R30.2 TP50.1 | length 23.9
  Top Layer w0.2: R30.2@37.45,96.043 R30.2@37.45,97.297
  Top Layer w0.3: R16.1@24.59,84.233 24.59,90.933 27.151,93.495 36.617,93.495 37.45,94.328 R30.2@37.45,96.043
  other v1: 31.45,96.028 33.45,96.028 41.45,96.028 31.45,98.028 33.45,98.028 41.45,98.028 31.45,100.028 33.45,100.028 35.45,100.028 37.45,100.028 39.45,100.028 41.45,100.028 31.45,102.028 33.45,102.028 35.45,102.028 37.45,102.028 39.45,102.028 41.45,102.028 33.45,104.028 35.45,104.028 37.45,104.028 39.45,104.028 41.45,104.028 33.45,106.028 35.45,106.028 37.45,106.028 39.45,106.028 41.45,106.028 33.45,108.028 35.45,108.028 37.45,108.028 39.45,108.028 41.45,108.028 33.45,110.028 35.45,110.028 37.45,110.028 39.45,110.028 41.45,110.028
NetC10_1: C10.1 D3.1 R15.2 | length 9.9
  Top Layer w0.3: D3.1@51.238,83.083 51.238,87.853 51.853,88.468 R15.2@53.95,88.468 55.95,88.468 C10.1@56.05,88.568
NetC10_2: C10.2 R18.1 U3.6 | length 4.8
  Top Layer w0.3: C10.2@56.05,86.468 C10.2@56.385,86.468 ; U3.6@56.385,83.825 C10.2@56.385,86.468 ; C10.2@56.385,86.646 C10.2@56.385,86.468 ; R18.1@57.9,86.668 57.7,86.468 C10.2@56.385,86.468
NetC11_1: C11.1 R12.1 | length 1.8
  Top Layer w1.5: R12.1@59.435,96 C11.1@61.25,96
NetC12_1: C12.1 R19.1 | length 1.8
  Top Layer w1.5: R19.1@68.535,96 C12.1@70.35,96
NetC12_2: C12.2 M4.1 R6.1 R21.1 R26.2 TP49.1 | length 24.1
  Top Layer w0.3: R6.1@66.69,84.233 66.69,91.246 68.988,93.544 78.817,93.544 79.45,94.178 R26.2@79.45,97.297
  other v1: 73.451,96.028 75.451,96.028 83.451,96.028 73.451,98.028 75.451,98.028 83.451,98.028 73.451,100.028 75.451,100.028 77.451,100.028 79.451,100.028 81.451,100.028 83.451,100.028 73.451,102.028 75.451,102.028 77.451,102.028 79.451,102.028 81.451,102.028 83.451,102.028 75.451,104.028 77.451,104.028 79.451,104.028 81.451,104.028 83.451,104.028 75.451,106.028 77.451,106.028 79.451,106.028 81.451,106.028 83.451,106.028 75.451,108.028 77.451,108.028 79.451,108.028 81.451,108.028 83.451,108.028 75.451,110.028 77.451,110.028 79.451,110.028 81.451,110.028 83.451,110.028
NetC15_1: C15.1 D5.1 R25.2 | length 4.3
  Top Layer w0.3: D5.1@94.671,88.409 96.521,88.409 96.716,88.603 C15.1@98.844,88.603
NetC15_2: C15.2 R28.1 U4.6 | length 4.8
  Top Layer w0.2: C15.2@98.844,86.468 C15.2@98.879,86.468 ; R28.1@100.594,86.468 R28.1@100.794,86.668 ; R28.1@100.751,86.71 R28.1@100.794,86.753
  Top Layer w0.3: U4.6@99.085,83.825 99.085,86.262 98.879,86.468 R28.1@100.594,86.468
NetC16_1: C16.1 R22.1 | length 1.8
  Top Layer w1.5: R22.1@101.285,96 C16.1@103.1,96
NetC17_1: C17.1 R29.1 | length 1.8
  Top Layer w1.5: R29.1@110.235,96 C17.1@112.05,96
NetC17_2: C17.2 M6.1 R31.1 R46.1 R48.2 TP55.1 | length 23.9
  Top Layer w0.2: R46.1@108.023,84.182 R46.1@108.023,84.19
  Top Layer w0.3: R46.1@108.184,84.19 108.184,89.738 111.984,93.538 118.876,93.538 119.45,94.113 R48.2@119.45,97.297
  Top Layer w0.5: 113.47,99.723 M6.1@113.47,101.854
  other v1: 115.45,96.028 117.45,96.028 125.45,96.028 115.45,98.028 117.45,98.028 125.45,98.028 115.45,100.028 117.45,100.028 119.45,100.028 121.45,100.028 123.45,100.028 125.45,100.028 115.45,102.028 117.45,102.028 119.45,102.028 121.45,102.028 123.45,102.028 125.45,102.028 117.45,104.028 119.45,104.028 121.45,104.028 123.45,104.028 125.45,104.028 117.45,106.028 119.45,106.028 121.45,106.028 123.45,106.028 125.45,106.028 117.45,108.028 119.45,108.028 121.45,108.028 123.45,108.028 125.45,108.028 117.451,110.028 119.451,110.028 121.451,110.028 123.451,110.028 125.451,110.028
NetC19_2: C19.2 R32.1 R35.1 U5.1 | length 6.6
  Top Layer w0.5: R32.1@14.286,10.522 14.375,10.611 C19.2@14.375,12.55 14.675,12.85 R35.1@16.64,12.85 ; U5.1@16.175,14.845 16.175,14.24 16.652,13.763 R35.1@16.652,12.85
NetC21_1: C21.1 D12.4 J5.1 L6.1 | length 6.1
  Top Layer w0.5: L6.1@115.789,7.047 115.84,7.097 D12.4@118.446,7.097 ; D12.4@118.675,7.097 D12.4@118.446,7.097 ; J5.1@118.83,4.1 118.83,5.106 118.446,5.491 D12.4@118.446,7.097
NetC24_1: C24.1 R34.2 U5.4 | length 4.7
  Top Layer w0.5: R34.2@14.4,21.05 14.425,21.075 C24.1@16.5,21.075 16.175,20.751 U5.4@16.175,18.655
NetC30_1: C30.1 D10.4 J4.1 L1.1 | length 9.8
  Top Layer w0.4: L1.1@95.432,8.073 95.432,7.048 C30.1@95.307,6.923 95.329,6.9 98.945,6.9 99.142,7.098 D10.4@100.575,7.098 100.396,6.918 100.396,5.511 100.73,5.177 J4.1@100.73,4.1
NetC33_1: C33.1 R6.2 R51.1 U7.4 | length 6.7
  Top Layer w0.2: U7.4@64.675,82.353 64.597,82.431 C33.1@62.385,82.431 62.385,83.928 R51.1@62.74,84.283 62.79,84.233 R6.2@64.99,84.233 R6.2@64.94,84.283
NetC34_1: C34.1 R16.2 R52.1 U8.4 | length 6.2
  Top Layer w0.2: U8.4@22.725,82.353 22.72,82.358 C34.1@20.61,82.358 20.69,82.439 20.69,84.233 R16.2@22.89,84.233
NetC37_1: C37.1 R46.2 R53.1 U9.4 | length 6.4
  Top Layer w0.2: U9.4@106.436,82.362 104.108,82.362 C37.1@104.061,82.409 104.061,83.801 R53.1@104.401,84.141 106.435,84.141 R46.2@106.484,84.19
NetC40_1: C40.1 R55.1 U15.1 U15.4 | length 8.9
  Top Layer w0.2: U15.4@81.418,71.883 81.418,72.514 81.604,72.7 82.661,72.7 83.324,73.364 U15.1@83.324,74.333 U15.1@83.1,74.109
  Top Layer w0.5: U15.1@83.324,74.333 85.715,74.333 C40.1@85.798,74.417 85.798,74.395 R55.1@88.01,74.395
NetC41_1: C41.1 R76.2 U1.12 | length 7.6
  Top Layer w0.2: U1.12@109.461,68.318 112.364,68.318 C41.1@112.531,68.484 113.356,67.659 115.517,67.659 R76.2@116.338,68.481
NetC42_1: C42.1 R73.2 U1.13 | length 8.1
  Top Layer w0.2: U1.13@109.461,68.968 110.499,68.968 111.816,70.284 C42.1@112.531,70.284 113.356,69.459 115.517,69.459 R73.2@116.338,70.281
NetC43_1: C43.1 R78.2 U1.11 | length 8
  Top Layer w0.2: U1.11@109.461,67.668 110.417,67.668 111.394,66.691 C43.1@112.53,66.691 113.418,65.803 115.461,65.803 R78.2@116.338,66.681
NetC46_1: C46.1 R114.2 U16.12 | length 8.1
  Top Layer w0.2: U16.12@109.461,59.646 110.728,59.646 111.346,59.028 C46.1@112.53,59.028 113.433,58.126 115.686,58.126 R114.2@116.588,59.028
NetC47_1: C47.1 R113.2 U16.13 | length 8
  Top Layer w0.2: U16.13@109.461,60.296 111.016,60.296 111.548,60.828 C47.1@112.53,60.828 113.355,60.003 115.763,60.003 R113.2@116.588,60.828
NetC48_1: C48.1 R115.2 U16.11 | length 9.3
  Top Layer w0.2: U16.11@109.461,58.996 110.613,58.996 110.956,58.653 110.956,57.476 111.204,57.228 C48.1@112.53,57.228 113.398,56.36 115.721,56.36 R115.2@116.588,57.228
NetC51_1: C51.1 Q8.3 Q8.6 R33.1 R36.2 TP40.1 U5.3 | length 20.7
  Top Layer w0.2: U5.3@16.175,17.385 18.775,17.385 C51.1@18.871,17.289 ; R36.2@18.964,18.768 18.871,18.676 C51.1@18.871,17.289 ; TP40.1@27.257,19.962 27.25,19.955 27.25,16.177 27.223,16.15 ; R33.1@28.85,16.15 27.223,16.15 ; C51.1@18.871,17.289 19.901,16.259 22.208,16.259 23.845,17.896 24.239,17.896 24.239,17.246 24.513,16.971 25.224,16.971 25.55,16.646 Q8.3@25.55,16.046 25.95,16.046 26.054,16.15 27.223,16.15
NetC52_1: C52.1 C54.1 Q8.2 Q10.1 Q11.5 Q11.6 R71.2 R119.1 R122.2 TP43.1 | length 57.8
  Top Layer w0.2: v1(8.05,15.5) R71.2@8.05,16.25 Q10.1@8.05,17.85 ; v1(23.699,12.925) Q11.6@24.25,12.925 24.25,14.251 24.485,14.486 24.9,14.486 ; 24.9,11.909 24.656,11.909 ; Q8.2@24.9,16.046 24.9,14.486 ; 25.25,11.909 25.144,11.909 ; R119.1@30.5,16.15 30.5,15.348 29.852,14.7 C52.1@28.29,14.7 28.29,13.698 28.133,13.542 27.271,13.542 26.837,13.108 26.837,12.418 26.328,11.909 25.144,11.909 ; TP43.1@34.622,11.599 C54.1@34.623,9.367 34.833,9.157 R122.2@34.833,7.842 34.008,8.667 32.488,8.667 32.283,8.462 32.283,8.446 31.36,7.523 24.063,7.523 22.698,8.888 22.698,11.496 23.111,11.909 24.656,11.909 ; 24.656,11.909 24.9,12.152 ; 24.9,12.152 Q11.5@24.9,12.925 24.9,14.486 ; 24.9,12.152 24.9,11.924 24.916,11.909 25.144,11.909 ; 24.9,12.152 25.144,11.909
  Bottom Layer w0.2: v1(8.05,15.5) 10.625,12.925 v1(23.699,12.925)
NetC53_1: C53.1 Q11.2 Q11.3 Q12.3 R120.1 TP42.1 | length 14.7
  Top Layer w0.2: Q11.2@24.9,11.075 24.9,9.588 C53.1@24.798,9.486 25.478,9.486 25.55,9.558 25.55,9.771 ; 25.55,10.21 25.55,10.204 ; Q12.3@27.491,9.875 27.383,9.983 25.772,9.983 ; TP42.1@31.7,12.7 30.571,11.571 29.029,11.571 R120.1@27.9,12.7 27.9,11.92 27.055,11.075 Q11.3@25.55,11.075 25.55,10.204 ; 25.55,9.771 25.55,9.983 ; 25.55,9.771 25.762,9.983 ; 25.55,9.983 25.762,9.983 ; 25.55,9.983 25.55,10.204 ; 25.55,10.204 25.772,9.983 ; 25.762,9.983 25.772,9.983
NetC57_1: C57.1 D13.1 Q1.1 R38.1 | length 8.8
  Top Layer w0.5: Q1.1@18.807,61.788 18.807,61.535 Q1.1@18.82,61.522 ; R38.1@18.82,58.706 Q1.1@18.82,61.522 ; C57.1@21.307,56.966 21.432,57.091 D13.1@21.432,58.91 Q1.1@18.82,61.522
NetC62_1: C62.1 D18.1 R93.2 U12.8 | length 4.3
  Top Layer w0.2: D18.1@104.499,30.01 104.461,30.048 U12.8@104.461,31.493 105.746,31.493 C62.1@105.867,31.614 107.117,31.614 R93.2@107.167,31.564 R93.2@107.198,31.595
NetCONN1_1: CONN1.1 D8.1 D9.2 F1.1 R38.2 TP58.1 | length 6.7
  Top Layer w1: D9.2@6.992,34.253 TP58.1@6.992,37.803 ; 18.801,53.834 18.82,53.854 R38.2@18.82,57.006
  other v1: 1.607,39.888 3.607,39.888 5.607,39.888 7.607,39.888 9.607,39.888 1.607,43.888 3.607,43.888 5.607,43.888 7.607,43.888 9.607,43.888 1.607,47.888 3.607,47.888 5.607,47.888 7.607,47.888 9.607,47.888 11.607,47.888 13.607,47.888 15.607,47.888 17.607,47.888 19.607,47.888 1.607,51.888 3.607,51.888 5.607,51.888 7.607,51.888 9.607,51.888 11.607,51.888 13.607,51.888 15.607,51.888 17.607,51.888 19.607,51.888
NetD7_2: D7.2 R117.2 | length 2.8
  Top Layer w0.5: D7.2@22.801,24.35 D7.2@23.115,24.037 23.243,23.909 R117.2@23.243,21.775
NetD9_1: D9.1 F2.2 | length 4.1
  Top Layer w1: D9.1@6.992,30.203 7.49,30.7 F2.2@10.9,30.7
NetD11_1: D11.1 R40.2 TP12.1 | length 5
  Top Layer w0.2: D11.1@3.1,10.4 R40.2@5.95,10.4 ; R40.2@5.65,10.35 TP12.1@7.65,10.35
  Top Layer w0.5: D11.1@3,10.3 D11.1@3.1,10.4
NetD14_1: D14.1 Q5.3 | length 3.3
  Top Layer w0.5: D14.1@3,26.3 3.771,25.529 Q5.3@5.95,25.529
NetD14_2: D14.2 R62.1 | length 7.8
  Top Layer w0.5: D14.2@3,28.4 4.247,28.4 4.865,27.782 8.699,27.782 R62.1@10.016,26.464
NetD15_1: D15.1 Q10.3 | length 3.2
  Top Layer w0.5: D15.1@3,18.3 4.336,18.3 4.836,18.8 Q10.3@5.95,18.8
NetD15_2: D15.2 R123.1 | length 3.6
  Top Layer w0.5: D15.2@3,20.4 4.1,21.5 R123.1@6.15,21.5
NetJ2_3: J2.3@128.46,43.129 J19.1 | length 12.2
  Top Layer w0.2: J19.1@120.407,50.483 120.407,48.558 125.836,43.129 J2.3@128.46,43.129
NetJ2_4: J2.4@131,43.129 J20.1 | length 13.1
  Top Layer w0.2: J20.1@123.407,50.483 123.407,46.323 125.401,44.329 129.8,44.329 J2.4@131,43.129
NetJ2_5: J2.5@128.46,40.589 J8.1 | length 32.3
  Top Layer w0.2: J8.1@108.407,50.483 108.407,49.533 108.722,49.218 109.657,49.218 110.065,49.627 110.065,52.627 110.966,53.528 117.914,53.528 118.556,52.885 118.556,48.944 126.911,40.589 J2.5@128.46,40.589
NetJ2_6: J2.6@131,40.589 J9.1 | length 50.6
  Top Layer w0.2: J9.1@93.407,50.483 93.407,49.66 93.747,49.319 94.262,49.319 95.022,50.08 95.022,53.427 95.745,54.15 118.256,54.15 119.101,53.304 119.101,49.116 126.354,41.862 129.727,41.862 J2.6@131,40.589
NetJ2_7: J2.7@128.46,38.049 J13.1 | length 23.7
  Top Layer w0.2: J13.1@111.407,50.483 111.407,49.458 111.77,49.095 114.348,49.095 116.474,46.969 119.048,46.969 125.136,40.882 125.136,39.407 126.493,38.049 J2.7@128.46,38.049
NetJ2_8: J2.8@131,38.049 J14.1 | length 22.7
  Top Layer w0.2: J14.1@114.407,50.483 114.407,49.774 116.762,47.419 119.235,47.419 125.608,41.046 125.608,40.123 126.482,39.249 129.66,39.249 130.86,38.049 J2.8@131,38.049
NetJ2_9: J2.9@128.46,35.509 J21.1 | length 46.3
  Top Layer w0.2: v1(96.407,36.68) J21.1@96.407,50.483
  Bottom Layer w0.2: v1(96.407,36.68) 98.016,36.68 98.638,36.058 107.251,36.058 107.8,35.509 J2.9@128.46,35.509
NetJ2_10: J2.10@131,35.509 J10.1 | length 47.2
  Top Layer w0.2: v1(98.907,36.708) 99.407,37.208 J10.1@99.407,50.483
  Bottom Layer w0.2: v1(98.907,36.708) 107.237,36.708 107.987,35.959 126.287,35.959 126.975,36.646 ; 126.975,36.709 129.8,36.709 J2.10@131,35.509
NetJ2_13: J2.13@128.46,30.429 J12.1 | length 38.2
  Top Layer w0.2: J12.1@102.407,50.483 102.407,49.635 104.341,47.701 114.417,47.701 116.049,46.069 118.575,46.069 123.91,40.735 123.91,34.979 J2.13@128.46,30.429
NetJ2_14: J2.14@131,30.429 J11.1 | length 37.7
  Top Layer w0.2: J11.1@105.407,50.483 105.407,49.638 106.758,48.287 114.468,48.287 116.236,46.519 118.762,46.519 124.36,40.921 124.36,35.202 127.793,31.769 129.66,31.769 J2.14@131,30.429
NetJ2_15: J2.15@128.46,27.889 J7.1 | length 39.2
  Top Layer w0.2: J7.1@117.407,50.483 117.407,48.889 v1@118.182,48.114
  Bottom Layer w0.2: v1(118.214,48.081) 130.886,48.081 132.593,46.374 132.593,29.844 131.838,29.089 129.66,29.089 J2.15@128.46,27.889
NetJ3_1: J3.1 R72.1 R78.1 TP5.1 | length 37.8
  Top Layer w0.2: R78.1@118.038,66.681 R72.1@119.838,66.681 120.663,65.856 123.713,65.856 TP5.1@123.838,65.981 123.838,66.956 132.456,75.574 132.456,91.917 132.184,92.19 J3.1@130.5,92.19
NetJ3_2: J3.2 R70.1 R76.1 TP2.1 | length 31.4
  Top Layer w0.2: R76.1@118.038,68.481 R70.1@119.838,68.481 119.863,68.481 120.688,67.656 123.013,67.656 TP2.1@123.838,68.481 132.006,76.648 132.006,88.458 131.775,88.69 J3.2@130.5,88.69
NetJ3_3: J3.3 R67.1 R73.1 TP1.1 | length 25
  Top Layer w0.2: R73.1@118.038,70.281 R67.1@119.838,70.281 120.663,69.456 123.187,69.456 123.838,70.107 TP1.1@123.838,70.981 128.654,75.796 128.654,84.573 129.27,85.19 J3.3@130.5,85.19
NetJ22_2: J22.2 R111.1 R115.1 TP17.1 | length 67.6
  Top Layer w0.2: R115.1@117.788,57.228 R111.1@119.838,57.228 119.838,56.122 120.138,55.822 122.98,55.822 TP17.1@123.838,56.681 126.018,58.86 126.018,63.783 133.806,71.571 133.806,108.816 132.852,109.77 J22.2@130.5,109.77
NetJ22_3: J22.3 R110.1 R114.1 TP14.1 | length 60.3
  Top Layer w0.2: R114.1@117.788,59.028 R110.1@119.838,59.028 120.068,59.028 120.893,59.853 123.166,59.853 TP14.1@123.838,59.181 125.223,60.566 125.223,63.625 133.356,71.757 133.356,105.825 132.91,106.27 J22.3@130.5,106.27
NetJ22_5: J22.5 R109.1 R113.1 TP18.1 | length 49.8
  Top Layer w0.2: R113.1@117.788,60.828 R109.1@119.838,60.828 120.691,61.681 TP18.1@123.838,61.681 123.838,62.876 132.906,71.944 132.906,98.685 132.32,99.27 J22.5@130.5,99.27
NetM1_2: M1.2 R7.2 R20.2 TP7.1 | length 7.3
  Top Layer w0.3: TP7.1@14.859,110.379 14.95,110.379 R20.2@14.95,108.5 14.75,108.3 M1.2@14.75,105.615 15.635,105.615 15.95,105.93 R7.2@16.985,105.93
